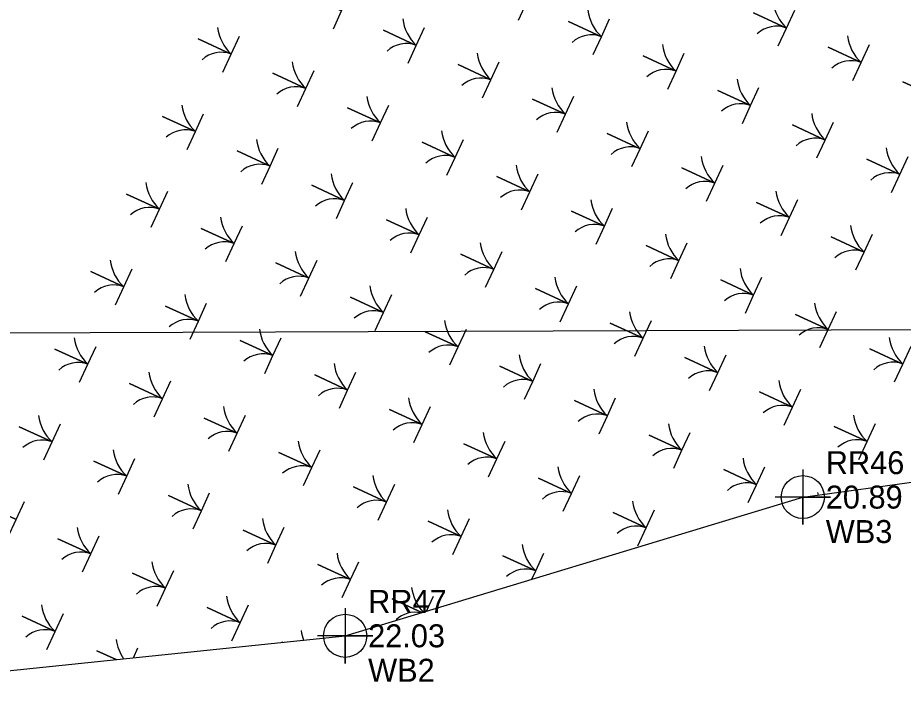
# Model space of a CAD drawing. Extents: x 2532037 to 2533565, y 713396 to 716867.
# Drawn here: x 2532589.9 to 2532686.3, y 715515.7 to 715588.4 of the extents above; entities that cross this region are included whole.
import ezdxf

# ---------------------------------------------------------------- set-up
doc = ezdxf.new("R2010")
doc.units = 0
for name, color, linetype in [('Exist Environmental Wetland Boundary', 7, 'Continuous'), ('Exist Environmental Wetland Boundary Cogo Comment', 7, 'Continuous'), ('Exist Environmental Wetland Boundary Cogo Elevation', 7, 'Continuous'), ('Exist Environmental Wetland Boundary Cogo Number', 7, 'Continuous'), ('Exist Environmental Wetland Boundary Cogo Point CELL', 7, 'Continuous'), ('Exist Property Line', 7, 'Continuous'), ('Scratch_Level_1', 7, 'Continuous')]:
    doc.layers.add(name, color=color, linetype=linetype)

msp = doc.modelspace()

# ---------------------------------------------------------------- linework, layer by layer
at = {"layer": 'Exist Environmental Wetland Boundary'}
for p, q in [((2532675.344, 715536.257), (2532729.855, 715543.754)), ((2532625.543, 715521.155), (2532675.344, 715536.257)), ((2532572.673, 715515.659), (2532625.543, 715521.155))]:
    msp.add_line(p, q, dxfattribs=at)
at = {"layer": 'Exist Environmental Wetland Boundary Cogo Point CELL'}
for points in [[(2532675.344, 715539.257), (2532675.344, 715533.257), (2532675.344, 715536.257), (2532678.344, 715536.257), (2532672.344, 715536.257)], [(2532625.543, 715524.155), (2532625.543, 715518.155), (2532625.543, 715521.155), (2532628.543, 715521.155), (2532622.543, 715521.155)]]:
    msp.add_lwpolyline(points, dxfattribs=at)
for centre in [(2532675.344, 715536.257), (2532625.543, 715521.155)]:
    msp.add_circle(centre, 2.344, dxfattribs=at)
at = {"layer": 'Exist Property Line'}
msp.add_line((2532798.465, 715554.88), (2532538.102, 715553.917), dxfattribs=at)
at = {"layer": 'Scratch_Level_1'}
for p, q in [((2532634.405, 715523.842), (2532635.158, 715525.473)), ((2532602.501, 715518.76), (2532602.996, 715519.833))]:
    msp.add_line(p, q, dxfattribs=at)
for points in [[(2532644.401, 715588.178), (2532645.302, 715590.13), (2532641.721, 715591.784), (2532645.302, 715590.13), (2532646.204, 715592.082)], [(2532624.26, 715587.232), (2532625.161, 715589.184), (2532621.579, 715590.838), (2532625.161, 715589.184), (2532626.063, 715591.137)], [(2532672.664, 715585.374), (2532673.565, 715587.326), (2532669.983, 715588.98), (2532673.565, 715587.326), (2532674.467, 715589.279)], [(2532652.523, 715584.428), (2532653.424, 715586.381), (2532649.842, 715588.034), (2532653.424, 715586.381), (2532654.325, 715588.333)], [(2532632.381, 715583.483), (2532633.283, 715585.435), (2532629.701, 715587.089), (2532633.283, 715585.435), (2532634.184, 715587.387)], [(2532612.24, 715582.537), (2532613.141, 715584.489), (2532609.559, 715586.143), (2532613.141, 715584.489), (2532614.043, 715586.442)], [(2532680.785, 715581.625), (2532681.687, 715583.577), (2532678.105, 715585.231), (2532681.687, 715583.577), (2532682.588, 715585.529)], [(2532660.644, 715580.679), (2532661.545, 715582.631), (2532657.964, 715584.285), (2532661.545, 715582.631), (2532662.447, 715584.584)], [(2532640.503, 715579.733), (2532641.404, 715581.686), (2532637.822, 715583.339), (2532641.404, 715581.686), (2532642.305, 715583.638)], [(2532620.361, 715578.788), (2532621.263, 715580.74), (2532617.681, 715582.394), (2532621.263, 715580.74), (2532622.164, 715582.692)], [(2532688.907, 715577.875), (2532689.808, 715579.828), (2532686.226, 715581.481), (2532689.808, 715579.828), (2532690.709, 715581.78)], [(2532668.765, 715576.93), (2532669.667, 715578.882), (2532666.085, 715580.536), (2532669.667, 715578.882), (2532670.568, 715580.834)], [(2532648.624, 715575.984), (2532649.525, 715577.936), (2532645.944, 715579.59), (2532649.525, 715577.936), (2532650.427, 715579.889)], [(2532628.483, 715575.038), (2532629.384, 715576.991), (2532625.802, 715578.644), (2532629.384, 715576.991), (2532630.285, 715578.943)], [(2532608.341, 715574.093), (2532609.243, 715576.045), (2532605.661, 715577.699), (2532609.243, 715576.045), (2532610.144, 715577.997)], [(2532676.887, 715573.18), (2532677.788, 715575.133), (2532674.206, 715576.786), (2532677.788, 715575.133), (2532678.69, 715577.085)], [(2532656.746, 715572.235), (2532657.647, 715574.187), (2532654.065, 715575.841), (2532657.647, 715574.187), (2532658.548, 715576.139)], [(2532636.604, 715571.289), (2532637.506, 715573.241), (2532633.924, 715574.895), (2532637.506, 715573.241), (2532638.407, 715575.194)], [(2532616.463, 715570.343), (2532617.364, 715572.296), (2532613.782, 715573.949), (2532617.364, 715572.296), (2532618.266, 715574.248)], [(2532685.008, 715569.431), (2532685.91, 715571.383), (2532682.328, 715573.037), (2532685.91, 715571.383), (2532686.811, 715573.336)], [(2532664.867, 715568.485), (2532665.768, 715570.438), (2532662.187, 715572.091), (2532665.768, 715570.438), (2532666.67, 715572.39)], [(2532644.726, 715567.54), (2532645.627, 715569.492), (2532642.045, 715571.146), (2532645.627, 715569.492), (2532646.528, 715571.444)], [(2532604.443, 715565.648), (2532605.344, 715567.601), (2532601.763, 715569.254), (2532605.344, 715567.601), (2532606.246, 715569.553)], [(2532624.584, 715566.594), (2532625.486, 715568.546), (2532621.904, 715570.2), (2532625.486, 715568.546), (2532626.387, 715570.499)], [(2532672.988, 715564.736), (2532673.89, 715566.688), (2532670.308, 715568.342), (2532673.89, 715566.688), (2532674.791, 715568.641)], [(2532652.847, 715563.79), (2532653.748, 715565.743), (2532650.167, 715567.396), (2532653.748, 715565.743), (2532654.65, 715567.695)], [(2532632.706, 715562.845), (2532633.607, 715564.797), (2532630.025, 715566.451), (2532633.607, 715564.797), (2532634.508, 715566.749)], [(2532612.564, 715561.899), (2532613.466, 715563.851), (2532609.884, 715565.505), (2532613.466, 715563.851), (2532614.367, 715565.804)], [(2532681.11, 715560.986), (2532682.011, 715562.939), (2532678.429, 715564.592), (2532682.011, 715562.939), (2532682.913, 715564.891)], [(2532660.969, 715560.041), (2532661.87, 715561.993), (2532658.288, 715563.647), (2532661.87, 715561.993), (2532662.771, 715563.946)], [(2532640.827, 715559.095), (2532641.729, 715561.048), (2532638.147, 715562.701), (2532641.729, 715561.048), (2532642.63, 715563)], [(2532620.686, 715558.15), (2532621.587, 715560.102), (2532618.005, 715561.756), (2532621.587, 715560.102), (2532622.489, 715562.054)], [(2532600.545, 715557.204), (2532601.446, 715559.156), (2532597.864, 715560.81), (2532601.446, 715559.156), (2532602.347, 715561.109)], [(2532669.09, 715556.291), (2532669.991, 715558.244), (2532666.409, 715559.897), (2532669.991, 715558.244), (2532670.893, 715560.196)], [(2532648.949, 715555.346), (2532649.85, 715557.298), (2532646.268, 715558.952), (2532649.85, 715557.298), (2532650.751, 715559.251)], [(2532628.807, 715554.4), (2532629.709, 715556.353), (2532626.127, 715558.006), (2532629.709, 715556.353), (2532630.61, 715558.305)], [(2532608.666, 715553.455), (2532609.567, 715555.407), (2532605.986, 715557.061), (2532609.567, 715555.407), (2532610.469, 715557.359)], [(2532677.211, 715552.542), (2532678.113, 715554.494), (2532674.531, 715556.148), (2532678.113, 715554.494), (2532679.014, 715556.447)], [(2532657.07, 715551.596), (2532657.971, 715553.549), (2532654.39, 715555.202), (2532657.971, 715553.549), (2532658.873, 715555.501)], [(2532636.929, 715550.651), (2532637.83, 715552.603), (2532634.248, 715554.257), (2532637.83, 715552.603), (2532638.731, 715554.556)], [(2532616.787, 715549.705), (2532617.689, 715551.658), (2532614.107, 715553.311), (2532617.689, 715551.658), (2532618.59, 715553.61)], [(2532596.646, 715548.76), (2532597.547, 715550.712), (2532593.966, 715552.366), (2532597.547, 715550.712), (2532598.449, 715552.664)], [(2532685.333, 715548.793), (2532686.234, 715550.745), (2532682.652, 715552.399), (2532686.234, 715550.745), (2532687.136, 715552.697)], [(2532665.192, 715547.847), (2532666.093, 715549.799), (2532662.511, 715551.453), (2532666.093, 715549.799), (2532666.994, 715551.752)], [(2532645.05, 715546.901), (2532645.952, 715548.854), (2532642.37, 715550.507), (2532645.952, 715548.854), (2532646.853, 715550.806)], [(2532624.909, 715545.956), (2532625.81, 715547.908), (2532622.228, 715549.562), (2532625.81, 715547.908), (2532626.712, 715549.861)], [(2532604.768, 715545.01), (2532605.669, 715546.963), (2532602.087, 715548.616), (2532605.669, 715546.963), (2532606.57, 715548.915)], [(2532673.313, 715544.098), (2532674.214, 715546.05), (2532670.632, 715547.704), (2532674.214, 715546.05), (2532675.116, 715548.002)], [(2532653.172, 715543.152), (2532654.073, 715545.104), (2532650.491, 715546.758), (2532654.073, 715545.104), (2532654.974, 715547.057)], [(2532633.03, 715542.206), (2532633.932, 715544.159), (2532630.35, 715545.812), (2532633.932, 715544.159), (2532634.833, 715546.111)], [(2532612.889, 715541.261), (2532613.79, 715543.213), (2532610.208, 715544.867), (2532613.79, 715543.213), (2532614.692, 715545.166)], [(2532592.748, 715540.315), (2532593.649, 715542.268), (2532590.067, 715543.921), (2532593.649, 715542.268), (2532594.55, 715544.22)], [(2532681.434, 715540.348), (2532682.336, 715542.301), (2532678.754, 715543.954), (2532682.336, 715542.301), (2532683.237, 715544.253)], [(2532661.293, 715539.403), (2532662.194, 715541.355), (2532658.613, 715543.009), (2532662.194, 715541.355), (2532663.096, 715543.308)], [(2532641.152, 715538.457), (2532642.053, 715540.409), (2532638.471, 715542.063), (2532642.053, 715540.409), (2532642.954, 715542.362)], [(2532621.01, 715537.511), (2532621.912, 715539.464), (2532618.33, 715541.117), (2532621.912, 715539.464), (2532622.813, 715541.416)], [(2532600.869, 715536.566), (2532601.77, 715538.518), (2532598.189, 715540.172), (2532601.77, 715538.518), (2532602.672, 715540.471)], [(2532669.415, 715535.653), (2532670.316, 715537.606), (2532666.734, 715539.259), (2532670.316, 715537.606), (2532671.217, 715539.558)], [(2532649.273, 715534.708), (2532650.175, 715536.66), (2532646.593, 715538.314), (2532650.175, 715536.66), (2532651.076, 715538.613)], [(2532629.132, 715533.762), (2532630.033, 715535.714), (2532626.451, 715537.368), (2532630.033, 715535.714), (2532630.935, 715537.667)], [(2532608.991, 715532.816), (2532609.892, 715534.769), (2532606.31, 715536.422), (2532609.892, 715534.769), (2532610.793, 715536.721)], [(2532588.849, 715531.871), (2532589.751, 715533.823), (2532586.169, 715535.477), (2532589.751, 715533.823), (2532590.652, 715535.776)], [(2532657.395, 715530.958), (2532658.296, 715532.911), (2532654.714, 715534.564), (2532658.296, 715532.911), (2532659.197, 715534.863)], [(2532637.253, 715530.013), (2532638.155, 715531.965), (2532634.573, 715533.619), (2532638.155, 715531.965), (2532639.056, 715533.918)], [(2532617.112, 715529.067), (2532618.013, 715531.019), (2532614.431, 715532.673), (2532618.013, 715531.019), (2532618.915, 715532.972)], [(2532596.971, 715528.121), (2532597.872, 715530.074), (2532594.29, 715531.727), (2532597.872, 715530.074), (2532598.773, 715532.026)], [(2532645.861, 715527.316), (2532646.276, 715528.216), (2532642.694, 715529.869), (2532646.276, 715528.216), (2532647.177, 715530.168)], [(2532625.233, 715525.318), (2532626.135, 715527.27), (2532622.553, 715528.924), (2532626.135, 715527.27), (2532627.036, 715529.223)], [(2532605.092, 715524.372), (2532605.993, 715526.325), (2532602.412, 715527.978), (2532605.993, 715526.325), (2532606.895, 715528.277)], [(2532613.214, 715520.623), (2532614.115, 715522.575), (2532610.533, 715524.229), (2532614.115, 715522.575), (2532615.016, 715524.528)], [(2532633.895, 715523.688), (2532630.674, 715525.174), (2532633.895, 715523.688)], [(2532593.072, 715519.677), (2532593.974, 715521.63), (2532590.392, 715523.283), (2532593.974, 715521.63), (2532594.875, 715523.582)], [(2532618.726, 715520.446), (2532618.654, 715520.479), (2532618.726, 715520.446)], [(2532600.615, 715518.564), (2532598.513, 715519.534), (2532600.615, 715518.564)]]:
    msp.add_lwpolyline(points, dxfattribs=at)
for centre, radius, start, end in [((2532676.852, 715590.832), 4.806, 187.34643, 226.84116), ((2532656.711, 715589.886), 4.806, 187.34643, 226.84116), ((2532636.57, 715588.941), 4.806, 187.34643, 226.84116), ((2532616.428, 715587.995), 4.806, 187.34643, 226.84116), ((2532672.481, 715584.449), 3.075, 69.35932, 132.75394), ((2532652.34, 715583.503), 3.075, 69.35932, 132.75394), ((2532684.974, 715587.082), 4.806, 187.34643, 226.84116), ((2532632.199, 715582.558), 3.075, 69.35932, 132.75394), ((2532664.833, 715586.137), 4.806, 187.34643, 226.84116), ((2532612.057, 715581.612), 3.075, 69.35932, 132.75394), ((2532644.691, 715585.191), 4.806, 187.34643, 226.84116), ((2532624.55, 715584.246), 4.806, 187.34643, 226.84116), ((2532680.603, 715580.7), 3.075, 69.35932, 132.75394), ((2532660.462, 715579.754), 3.075, 69.35932, 132.75394), ((2532640.32, 715578.808), 3.075, 69.35932, 132.75394), ((2532672.954, 715582.387), 4.806, 187.34643, 226.84116), ((2532620.179, 715577.863), 3.075, 69.35932, 132.75394), ((2532652.813, 715581.442), 4.806, 187.34643, 226.84116), ((2532632.671, 715580.496), 4.806, 187.34643, 226.84116), ((2532612.53, 715579.551), 4.806, 187.34643, 226.84116), ((2532668.583, 715576.005), 3.075, 69.35932, 132.75394), ((2532648.442, 715575.059), 3.075, 69.35932, 132.75394), ((2532681.075, 715578.638), 4.806, 187.34643, 226.84116), ((2532628.3, 715574.113), 3.075, 69.35932, 132.75394), ((2532660.934, 715577.692), 4.806, 187.34643, 226.84116), ((2532608.159, 715573.168), 3.075, 69.35932, 132.75394), ((2532640.793, 715576.747), 4.806, 187.34643, 226.84116), ((2532620.651, 715575.801), 4.806, 187.34643, 226.84116), ((2532656.563, 715571.31), 3.075, 69.35932, 132.75394), ((2532676.704, 715572.255), 3.075, 69.35932, 132.75394), ((2532636.422, 715570.364), 3.075, 69.35932, 132.75394), ((2532689.197, 715574.889), 4.806, 187.34643, 226.84116), ((2532616.28, 715569.418), 3.075, 69.35932, 132.75394), ((2532669.056, 715573.943), 4.806, 187.34643, 226.84116), ((2532648.914, 715572.997), 4.806, 187.34643, 226.84116), ((2532684.826, 715568.506), 3.075, 69.35932, 132.75394), ((2532628.773, 715572.052), 4.806, 187.34643, 226.84116), ((2532664.685, 715567.56), 3.075, 69.35932, 132.75394), ((2532608.632, 715571.106), 4.806, 187.34643, 226.84116), ((2532644.543, 715566.615), 3.075, 69.35932, 132.75394), ((2532677.177, 715570.194), 4.806, 187.34643, 226.84116), ((2532624.402, 715565.669), 3.075, 69.35932, 132.75394), ((2532657.036, 715569.248), 4.806, 187.34643, 226.84116), ((2532604.261, 715564.723), 3.075, 69.35932, 132.75394), ((2532636.894, 715568.302), 4.806, 187.34643, 226.84116), ((2532616.753, 715567.357), 4.806, 187.34643, 226.84116), ((2532672.806, 715563.811), 3.075, 69.35932, 132.75394), ((2532652.665, 715562.865), 3.075, 69.35932, 132.75394), ((2532685.298, 715566.444), 4.806, 187.34643, 226.84116), ((2532632.523, 715561.92), 3.075, 69.35932, 132.75394), ((2532665.157, 715565.499), 4.806, 187.34643, 226.84116), ((2532612.382, 715560.974), 3.075, 69.35932, 132.75394), ((2532645.016, 715564.553), 4.806, 187.34643, 226.84116), ((2532624.874, 715563.607), 4.806, 187.34643, 226.84116), ((2532680.927, 715560.062), 3.075, 69.35932, 132.75394), ((2532604.733, 715562.662), 4.806, 187.34643, 226.84116), ((2532660.786, 715559.116), 3.075, 69.35932, 132.75394), ((2532640.645, 715558.17), 3.075, 69.35932, 132.75394), ((2532673.279, 715561.749), 4.806, 187.34643, 226.84116), ((2532620.503, 715557.225), 3.075, 69.35932, 132.75394), ((2532653.137, 715560.804), 4.806, 187.34643, 226.84116), ((2532600.362, 715556.279), 3.075, 69.35932, 132.75394), ((2532632.996, 715559.858), 4.806, 187.34643, 226.84116), ((2532612.855, 715558.912), 4.806, 187.34643, 226.84116), ((2532668.908, 715555.367), 3.075, 69.35932, 132.75394), ((2532648.766, 715554.421), 3.075, 69.35932, 132.75394), ((2532681.4, 715558), 4.806, 187.34643, 226.84116), ((2532628.625, 715553.475), 3.075, 69.35932, 132.75394), ((2532661.259, 715557.054), 4.806, 187.34643, 226.84116), ((2532608.484, 715552.53), 3.075, 69.35932, 132.75394), ((2532641.117, 715556.109), 4.806, 187.34643, 226.84116), ((2532620.976, 715555.163), 4.806, 187.34643, 226.84116), ((2532677.029, 715551.617), 3.075, 69.35932, 132.75394), ((2532600.835, 715554.218), 4.806, 187.34643, 226.84116), ((2532656.888, 715550.672), 3.075, 69.35932, 132.75394), ((2532689.521, 715554.251), 4.806, 187.34643, 226.84116), ((2532636.746, 715549.726), 3.075, 69.35932, 132.75394), ((2532669.38, 715553.305), 4.806, 187.34643, 226.84116), ((2532616.605, 715548.78), 3.075, 69.35932, 132.75394), ((2532649.239, 715552.359), 4.806, 187.34643, 226.84116), ((2532596.464, 715547.835), 3.075, 69.35932, 132.75394), ((2532629.097, 715551.414), 4.806, 187.34643, 226.84116), ((2532685.15, 715547.868), 3.075, 69.35932, 132.75394), ((2532608.956, 715550.468), 4.806, 187.34643, 226.84116), ((2532665.009, 715546.922), 3.075, 69.35932, 132.75394), ((2532644.868, 715545.977), 3.075, 69.35932, 132.75394), ((2532677.502, 715549.556), 4.806, 187.34643, 226.84116), ((2532624.726, 715545.031), 3.075, 69.35932, 132.75394), ((2532657.36, 715548.61), 4.806, 187.34643, 226.84116), ((2532604.585, 715544.085), 3.075, 69.35932, 132.75394), ((2532637.219, 715547.664), 4.806, 187.34643, 226.84116), ((2532617.078, 715546.719), 4.806, 187.34643, 226.84116), ((2532673.131, 715543.173), 3.075, 69.35932, 132.75394), ((2532596.936, 715545.773), 4.806, 187.34643, 226.84116), ((2532652.989, 715542.227), 3.075, 69.35932, 132.75394), ((2532685.623, 715545.806), 4.806, 187.34643, 226.84116), ((2532632.848, 715541.282), 3.075, 69.35932, 132.75394), ((2532665.482, 715544.861), 4.806, 187.34643, 226.84116), ((2532612.707, 715540.336), 3.075, 69.35932, 132.75394), ((2532645.34, 715543.915), 4.806, 187.34643, 226.84116), ((2532592.565, 715539.39), 3.075, 69.35932, 132.75394), ((2532625.199, 715542.969), 4.806, 187.34643, 226.84116), ((2532681.252, 715539.423), 3.075, 69.35932, 132.75394), ((2532605.058, 715542.024), 4.806, 187.34643, 226.84116), ((2532661.111, 715538.478), 3.075, 69.35932, 132.75394), ((2532640.969, 715537.532), 3.075, 69.35932, 132.75394), ((2532673.603, 715541.111), 4.806, 187.34643, 226.84116), ((2532600.687, 715535.641), 3.075, 69.35932, 132.75394), ((2532620.828, 715536.587), 3.075, 69.35932, 132.75394), ((2532653.462, 715540.166), 4.806, 187.34643, 226.84116), ((2532633.32, 715539.22), 4.806, 187.34643, 226.84116), ((2532669.232, 715534.729), 3.075, 69.35932, 132.75394), ((2532613.179, 715538.274), 4.806, 187.34643, 226.84116), ((2532649.091, 715533.783), 3.075, 69.35932, 132.75394), ((2532628.949, 715532.837), 3.075, 69.35932, 132.75394), ((2532681.725, 715537.362), 4.806, 187.34643, 190.51761), ((2532608.808, 715531.892), 3.075, 69.35932, 132.75394), ((2532661.583, 715536.416), 4.806, 187.34643, 226.84116), ((2532621.301, 715534.525), 4.806, 187.34643, 226.84116), ((2532641.442, 715535.471), 4.806, 187.34643, 226.84116), ((2532601.159, 715533.579), 4.806, 187.34643, 226.84116), ((2532657.212, 715530.034), 3.075, 69.35932, 132.75394), ((2532637.071, 715529.088), 3.075, 69.35932, 132.75394), ((2532616.93, 715528.142), 3.075, 69.35932, 132.75394), ((2532649.563, 715531.721), 4.806, 187.34643, 226.84116), ((2532596.788, 715527.197), 3.075, 69.35932, 132.75394), ((2532629.422, 715530.776), 4.806, 187.34643, 226.84116), ((2532609.281, 715529.83), 4.806, 187.34643, 226.84116), ((2532645.192, 715525.339), 3.075, 69.35932, 132.75394), ((2532625.051, 715524.393), 3.075, 69.35932, 132.75394), ((2532604.91, 715523.447), 3.075, 69.35932, 132.75394), ((2532637.543, 715527.026), 4.806, 187.34643, 223.26164), ((2532617.402, 715526.081), 4.806, 187.34643, 226.84116), ((2532597.261, 715525.135), 4.806, 187.34643, 226.84116), ((2532633.172, 715520.644), 3.075, 78.42795, 132.75394), ((2532613.031, 715519.698), 3.075, 69.35932, 132.75394), ((2532592.89, 715518.752), 3.075, 69.35932, 132.75394), ((2532625.524, 715522.331), 4.806, 187.34643, 200.05056), ((2532605.382, 715521.386), 4.806, 187.34643, 214.71908)]:
    msp.add_arc(centre, radius, start, end, dxfattribs=at)

# ---------------------------------------------------------------- texts
at = {"layer": 'Exist Environmental Wetland Boundary Cogo Comment'}
for s, p in [('WB3', (2532677.844, 715531.257)), ('WB2', (2532628.043, 715516.155))]:
    msp.add_text(s, height=2.5, dxfattribs=at).set_placement(p)
at = {"layer": 'Exist Environmental Wetland Boundary Cogo Elevation'}
for s, p in [('20.89', (2532677.844, 715535.007)), ('22.03', (2532628.043, 715519.905))]:
    msp.add_text(s, height=2.5, dxfattribs=at).set_placement(p)
at = {"layer": 'Exist Environmental Wetland Boundary Cogo Number'}
for s, p in [('RR46', (2532677.844, 715538.757)), ('RR47', (2532628.043, 715523.655))]:
    msp.add_text(s, height=2.5, dxfattribs=at).set_placement(p)

doc.saveas('drawing.dxf')
